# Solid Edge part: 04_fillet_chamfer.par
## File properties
Author: edge
Template: Normal.par
Last saved by: edge
Revision: 29
Application: Solid Edge
非切断部品: False
文書内容のタイプ: 0
Accuracy: 0.99
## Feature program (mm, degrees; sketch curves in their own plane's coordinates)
sketch for "unnamed Protrusion 1" plane through (0, 0, 0) normal (0, 0, 1) x-axis (1, 0, 0)
  circle centre (0, 0) radius 40
extrude "unnamed Protrusion 1" add finite 73.025 along +normal
sketch for "突き出し_2" plane through (0, 0, 0) normal (0, 0, 1) x-axis (1, 0, 0)
  line (0, 40) -> (0, -40)
  line (0, -40) -> (150, -40)
  line (150, -40) -> (150, 40)
  line (150, 40) -> (0, 40)
  dimension (linear) = 150
extrude "突き出し_2" add finite 25.4 along +normal
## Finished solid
Body 1: solid body, 7 faces, 13 edges, 8 vertices.
  Faces by surface: plane 6, cylinder 1
  Edges by curve: line 10, circle 3
Bounding box of the edges (mm): 190.000 x 80.000 x 73.025, from (-40, -40, 0) to (150, 40, 73.025).
Cylindrical faces by radius (mm): R40 x1
Planar faces by outward normal: +x 1, +y 1, +z 2, -y 1, -z 1
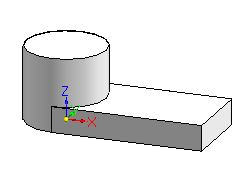
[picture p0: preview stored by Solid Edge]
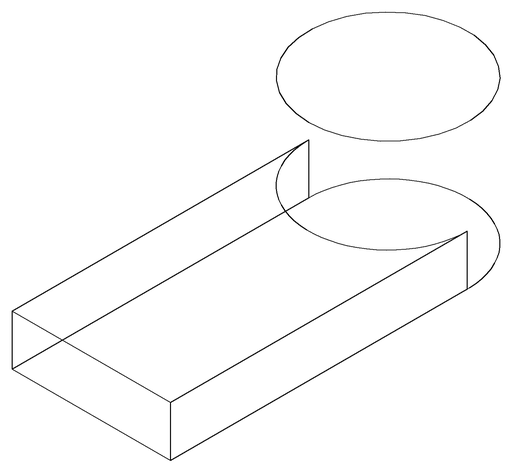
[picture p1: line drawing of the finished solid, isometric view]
